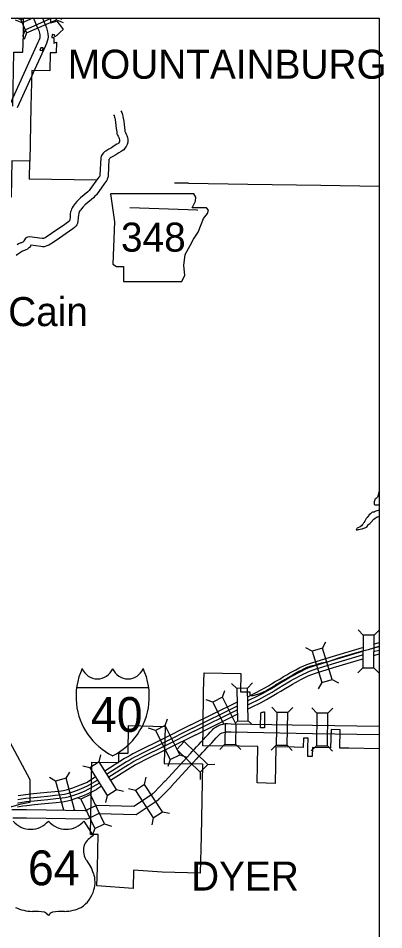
# Model space of a CAD drawing. Extents: x 535214 to 694517, y 381272 to 484355.
# Drawn here: x 559659 to 566314, y 463649 to 480223 of the extents above; entities that cross this region are included whole.
import ezdxf

# ---------------------------------------------------------------- set-up
doc = ezdxf.new("R2010")
doc.units = 0
for name, color, linetype in [('1', 7, 'Continuous'), ('Level 11', 7, 'Continuous'), ('Level 15', 7, 'Continuous'), ('Level 19', 7, 'Continuous'), ('Level 20', 7, 'Continuous'), ('Level 21', 7, 'Continuous'), ('Level 22', 7, 'Continuous'), ('Level 23', 7, 'Continuous'), ('Level 24', 7, 'Continuous'), ('Level 6', 7, 'Continuous'), ('Level 8', 7, 'Continuous'), ('Level 9', 7, 'Continuous')]:
    doc.layers.add(name, color=color, linetype=linetype)

msp = doc.modelspace()

# ---------------------------------------------------------------- linework, layer by layer
at = {"layer": '1'}
msp.add_lwpolyline([(535214, 480223), (566227, 480223), (566227, 448175), (535214, 448175)], close=True, dxfattribs=at)
at = {"layer": 'Level 11'}
for points in [[(561529, 478538), (561544, 478509), (561558, 478470), (561565, 478439), (561572, 478405), (561580, 478349), (561587, 478289), (561593, 478239), (561601, 478180), (561603, 478161), (561604, 478160), (561610, 478148), (561625, 478118), (561636, 478090), (561648, 478052), (561656, 478017), (561655, 477972), (561644, 477927), (561627, 477891), (561603, 477858), (561579, 477832), (561554, 477815), (561535, 477803), (561488, 477774), (561434, 477740), (561384, 477711), (561336, 477683), (561325, 477675), (561318, 477669), (561313, 477663), (561312, 477659)], [(561395, 478469), (561406, 478449), (561414, 478426), (561419, 478407), (561424, 478380), (561431, 478329), (561438, 478272), (561444, 478221), (561452, 478159), (561457, 478123), (561467, 478097), (561477, 478079), (561488, 478056), (561495, 478039), (561503, 478014), (561505, 478002), (561505, 477991), (561502, 477977), (561497, 477967), (561488, 477954), (561480, 477946), (561471, 477940), (561457, 477931), (561408, 477901), (561356, 477868), (561309, 477841), (561254, 477809), (561231, 477792), (561210, 477773), (561187, 477746), (561171, 477715), (561162, 477683)], [(561162, 477683), (561145, 477371), (561143, 477358), (561142, 477354), (561139, 477348), (561135, 477342), (561104, 477301), (560966, 477111), (560948, 477091), (560925, 477069), (560795, 476957), (560772, 476938), (560755, 476920), (560725, 476889), (560694, 476854), (560675, 476828), (560658, 476804), (560640, 476774), (560629, 476752), (560621, 476730), (560614, 476701), (560608, 476669), (560603, 476609), (560598, 476559), (560595, 476544), (560595, 476544), (560592, 476539), (560589, 476536), (560580, 476527), (560558, 476508), (560509, 476473), (560265, 476307), (560170, 476241), (560153, 476232), (560134, 476224), (560118, 476219), (560110, 476218), (560102, 476217), (560093, 476218), (559867, 476251), (559828, 476241), (559795, 476223), (559772, 476196), (559763, 476178), (559760, 476169), (559759, 476167), (559756, 476164), (559748, 476157), (559741, 476150), (559732, 476146), (559721, 476141), (559705, 476137), (559667, 476119), (559638, 476101)], [(561311, 477660), (561294, 477355), (561290, 477326), (561281, 477297), (561270, 477275), (561260, 477259), (561225, 477212), (561082, 477015), (561056, 476987), (561028, 476959), (560892, 476843), (560875, 476828), (560863, 476816), (560836, 476787), (560811, 476759), (560797, 476741), (560784, 476723), (560771, 476700), (560766, 476691), (560764, 476687), (560761, 476671), (560757, 476651), (560753, 476595), (560747, 476536), (560738, 476493), (560725, 476468), (560712, 476448), (560697, 476432), (560681, 476416), (560651, 476391), (560595, 476350), (560350, 476183), (560250, 476114), (560219, 476097), (560183, 476082), (560152, 476073), (560129, 476069), (560100, 476066), (560073, 476070), (559892, 476096), (559881, 476079), (559862, 476057), (559846, 476043), (559827, 476026), (559798, 476011), (559771, 475999), (559757, 475995), (559738, 475986), (559718, 475975), (559667, 475941), (559622, 475911)]]:
    msp.add_lwpolyline(points, dxfattribs=at)
at = {"layer": 'Level 15'}
for points in [[(559938, 480223), (559946, 480205), (559995, 480094), (560018, 480039), (560033, 480003), (560046, 479950), (560050, 479924), (560051, 479886), (560050, 479868), (560046, 479850), (560035, 479819), (560019, 479785), (559505, 478654)], [(560102, 480223), (560133, 480152), (560156, 480096), (560175, 480050), (560194, 479978), (560199, 479937), (560202, 479885), (560199, 479844), (560189, 479805), (560174, 479763), (560156, 479723), (559641, 478593)], [(562794, 466855), (562827, 466891), (562868, 466933), (562906, 466975), (562947, 467017), (562990, 467064), (563031, 467108), (563070, 467150), (563114, 467199), (563154, 467241), (563196, 467286), (563215, 467307), (563235, 467321), (563255, 467335), (563278, 467350), (563298, 467359), (563320, 467369), (563355, 467379), (563387, 467389), (563431, 467397), (563471, 467397), (563538, 467396), (565018, 467368), (566227, 467351)], [(562903, 466753), (562935, 466787), (562977, 466829), (563016, 466872), (563056, 466914), (563100, 466962), (563141, 467006), (563181, 467049), (563224, 467097), (563263, 467138), (563305, 467183), (563315, 467194), (563322, 467199), (563338, 467210), (563350, 467218), (563360, 467222), (563373, 467228), (563397, 467235), (563422, 467243), (563445, 467247), (563470, 467247), (563536, 467246), (565015, 467218), (566227, 467201)], [(562793, 466855), (562333, 466353)], [(562904, 466754), (562443, 466251)], [(559543, 465836), (559810, 465834), (560876, 465816), (560884, 465816), (560891, 465819), (560921, 465834), (561088, 465913), (561762, 465898), (562106, 466122), (562117, 466130), (562128, 466140), (562334, 466354)], [(559561, 465686), (559808, 465684), (560879, 465666), (560908, 465667), (560931, 465673), (560954, 465683), (560986, 465699), (561120, 465762), (561805, 465747), (562190, 465998), (562212, 466013), (562233, 466033), (562442, 466250)]]:
    msp.add_lwpolyline(points, dxfattribs=at)
at = {"layer": 'Level 19'}
for points in [[(563836, 467886), (563980, 467955), (564084, 468009), (564213, 468085), (564269, 468119), (564337, 468161), (564419, 468208), (564491, 468251), (564551, 468286), (564604, 468319), (564667, 468353), (564710, 468377), (564787, 468416), (564858, 468450), (564915, 468473), (565005, 468505), (565339, 468607), (565926, 468782)], [(566128, 468843), (566227, 468872)], [(566129, 468706), (566227, 468735)], [(566134, 468773), (566227, 468801)], [(563836, 467739), (563888, 467765), (564039, 467838), (564147, 467895), (564279, 467972), (564337, 468006), (564404, 468048), (564485, 468095), (564557, 468138), (564618, 468173), (564670, 468205), (564730, 468238), (564772, 468261), (564845, 468298), (564911, 468329), (564962, 468350), (565046, 468380), (565377, 468482), (565928, 468646)], [(563844, 467813), (563860, 467821), (564011, 467894), (564117, 467949), (564248, 468026), (564305, 468060), (564372, 468102), (564453, 468149), (564526, 468192), (564586, 468227), (564639, 468259), (564700, 468293), (564743, 468316), (564818, 468354), (564885, 468387), (564939, 468409), (565026, 468440), (565359, 468542), (565932, 468712)], [(563846, 467668), (563918, 467703), (564070, 467777), (564181, 467834), (564314, 467913), (564373, 467948), (564440, 467989), (564520, 468036), (564592, 468079), (564653, 468114), (564705, 468146), (564763, 468178), (564804, 468200), (564875, 468237), (564938, 468266), (564986, 468286), (565068, 468315), (565397, 468416), (565933, 468575)], [(566133, 468635), (566227, 468664)], [(562802, 467375), (563641, 467790)], [(562833, 467313), (563639, 467712)], [(562860, 467257), (563647, 467647)], [(562891, 467196), (563646, 467569)], [(562802, 467375), (562275, 467111), (561842, 466899), (561797, 466874), (561747, 466848), (561696, 466820), (561642, 466788), (561596, 466762), (561237, 466535)], [(562833, 467313), (562306, 467050), (561874, 466837), (561829, 466813), (561779, 466788), (561731, 466760), (561677, 466728), (561632, 466703), (561269, 466474)], [(562861, 467257), (562333, 466994), (561902, 466782), (561858, 466758), (561809, 466733), (561762, 466706), (561708, 466674), (561664, 466649), (561306, 466423)], [(562891, 467196), (562364, 466932), (561934, 466721), (561890, 466697), (561842, 466672), (561797, 466647), (561743, 466615), (561699, 466590), (561338, 466363)], [(561063, 466426), (560918, 466334)], [(559651, 465953), (559665, 465957), (559731, 465969), (559806, 465980), (559951, 465994), (560069, 466006), (560201, 466018), (560342, 466033), (560459, 466045), (560512, 466053), (560593, 466075), (560692, 466104), (560792, 466140), (560880, 466176), (560947, 466210), (561144, 466321)], [(559652, 466018), (559721, 466031), (559799, 466042), (559945, 466056), (560063, 466068), (560195, 466080), (560335, 466095), (560452, 466107), (560499, 466114), (560576, 466135), (560672, 466164), (560769, 466198), (560854, 466233), (560918, 466265), (561105, 466371)], [(559659, 466089), (559710, 466099), (559791, 466110), (559938, 466124), (560057, 466136), (560188, 466148), (560328, 466163), (560443, 466175), (560485, 466182), (560557, 466201), (560651, 466229), (560745, 466263), (560918, 466334)], [(561175, 466260), (561083, 466201)], [(559646, 465882), (559679, 465890), (559742, 465901), (559814, 465911), (559958, 465925), (560076, 465937), (560208, 465949), (560349, 465964), (560468, 465977), (560526, 465985), (560612, 466008), (560713, 466039), (560816, 466076), (560909, 466114), (561083, 466201)]]:
    msp.add_lwpolyline(points, dxfattribs=at)
at = {"layer": 'Level 20'}
for p, q in [((559733, 480138), (559610, 480186)), ((559708, 480196), (559639, 480223)), ((560357, 480196), (560480, 480148)), ((560409, 480223), (560454, 480206)), ((559787, 480015), (559739, 479892)), ((559813, 479957), (559765, 479834)), ((565938, 469006), (565845, 469100)), ((566136, 469005), (566227, 469096)), ((565009, 468712), (564892, 468774)), ((565198, 468770), (565260, 468887)), ((565935, 468412), (565841, 468319)), ((566133, 468411), (566226, 468318)), ((563636, 468037), (563541, 468129)), ((563834, 468041), (563925, 468136)), ((565183, 468144), (565121, 468028)), ((565372, 468202), (565489, 468140)), ((563380, 467876), (563423, 468001)), ((563834, 468041), (563636, 468037)), ((563636, 468037), (563648, 467443)), ((563846, 467447), (563834, 468041)), ((563203, 467788), (563078, 467830)), ((563380, 467876), (563203, 467788)), ((563203, 467788), (563397, 467396)), ((563619, 467394), (563380, 467876)), ((564367, 467602), (564276, 467697)), ((564565, 467599), (564660, 467690)), ((565097, 467589), (565005, 467684)), ((565295, 467586), (565389, 467678)), ((562335, 467361), (562377, 467487)), ((563648, 467443), (563624, 467418)), ((563648, 467443), (563846, 467447)), ((563846, 467447), (563903, 467392)), ((562158, 467273), (562033, 467314)), ((563426, 467398), (563421, 467021)), ((563619, 467018), (563624, 467392)), ((562683, 467070), (562545, 466928)), ((562683, 467070), (562683, 467088)), ((563109, 466656), (562683, 467070)), ((562545, 466928), (562971, 466514)), ((563421, 467021), (563327, 466929)), ((563421, 467021), (563619, 467018)), ((563619, 467018), (563711, 466924)), ((564356, 467008), (564261, 466917)), ((564554, 467005), (564645, 466910)), ((565088, 466995), (564994, 466903)), ((565286, 466992), (565378, 466898)), ((561131, 466701), (561161, 466830)), ((562424, 466742), (562382, 466616)), ((562601, 466830), (562726, 466788)), ((560964, 466596), (560835, 466625)), ((562971, 466514), (563109, 466656)), ((563109, 466656), (563241, 466658)), ((560341, 466352), (560226, 466417)), ((560532, 466403), (560598, 466517)), ((561959, 466292), (561986, 466421)), ((562971, 466514), (562973, 466382)), ((560532, 466403), (560341, 466352)), ((560341, 466352), (560481, 465829)), ((560686, 465829), (560532, 466403)), ((560976, 466111), (560797, 466026)), ((560976, 466111), (560991, 466152)), ((561230, 465574), (560976, 466111)), ((561281, 466093), (561251, 465965)), ((561448, 466199), (561577, 466170)), ((561793, 466184), (561664, 466211)), ((560797, 466026), (560740, 466046)), ((560797, 466026), (561051, 465489)), ((560668, 465824), (560686, 465829)), ((560686, 465829), (560697, 465822)), ((562283, 465794), (562413, 465767)), ((562117, 465686), (562090, 465557)), ((561051, 465489), (561007, 465365)), ((561051, 465489), (561230, 465574)), ((561230, 465574), (561355, 465530))]:
    msp.add_line(p, q, dxfattribs=at)
for points in [[(559769, 480223), (559708, 480196), (559787, 480015), (560262, 480223)], [(559927, 480223), (559733, 480138), (559813, 479957), (560357, 480196), (560345, 480223)]]:
    msp.add_lwpolyline(points, dxfattribs=at)
for points in [[(566133, 468411), (566136, 469005), (565938, 469006), (565935, 468412)], [(565372, 468202), (565198, 468770), (565009, 468712), (565183, 468144)], [(564367, 467602), (564356, 467008), (564554, 467005), (564565, 467599)], [(565286, 466992), (565295, 467586), (565097, 467589), (565088, 466995)], [(562601, 466830), (562335, 467361), (562158, 467273), (562424, 466742)], [(561448, 466199), (561131, 466701), (560964, 466596), (561281, 466093)], [(561793, 466184), (562117, 465686), (562283, 465794), (561959, 466292)]]:
    msp.add_lwpolyline(points, close=True, dxfattribs=at)
at = {"layer": 'Level 21'}
msp.add_lwpolyline([(561338, 477029), (561414, 476522), (561380, 475752), (561448, 475710), (561574, 475710), (561574, 475439), (562640, 475439), (562691, 475549), (562674, 475727), (562699, 475930), (562792, 476090), (562852, 476209), (562936, 476336), (562987, 476471), (563029, 476581), (563105, 476674), (563122, 476733), (563089, 476776), (562826, 476776), (562886, 476894), (562894, 476970), (562859, 477029)], close=True, dxfattribs=at)
at = {"layer": 'Level 22'}
msp.add_line((560852, 465626), (561025, 465358), dxfattribs=at)
for centre, radius, start, end in [((559888, 465897), 421, 220.075, 319.6701), ((560530, 465897), 421, 220.3299, 319.925), ((561251, 464970), 450, 120.0117, 149.2191), ((561153, 465088), 308, 158.7892, 211.1895), ((560346, 464456), 719, 17.3087, 41.0435), ((560584, 464515), 475, 342.6181, 19.0424), ((560506, 464517), 550, 302.8688, 344.8926), ((559921, 464690), 706, 244.0771, 269.5779), ((559938, 462691), 1293, 81.1942, 90.9539), ((560099, 463850), 124, 28.0342, 72.9864), ((560318, 463850), 124, 107.0136, 151.9658), ((560480, 462691), 1293, 89.0461, 98.8058), ((560496, 464690), 706, 270.4221, 295.9229)]:
    msp.add_arc(centre, radius, start, end, dxfattribs=at)
at = {"layer": 'Level 23'}
msp.add_line((560723, 468054), (562034, 468054), dxfattribs=at)
for centre, radius, start, end in [((561941, 467883), 1230, 155.2204, 185.7928), ((561102, 468511), 300, 202.1459, 337.3414), ((561655, 468511), 300, 202.6586, 337.8541), ((560816, 467883), 1230, 354.2072, 24.7796), ((561919, 467893), 1209, 186.3923, 243.4571), ((560838, 467893), 1209, 296.5429, 353.6077)]:
    msp.add_arc(centre, radius, start, end, dxfattribs=at)
at = {"layer": 'Level 6'}
for points in [[(559754, 479934), (559756, 480223)], [(560250, 480223), (560249, 480142), (560360, 480170), (560445, 480059), (560475, 480018), (560421, 479969), (560374, 479922), (560366, 479915), (560361, 479911), (560356, 479907), (560351, 479904), (560344, 479900), (560331, 479894), (560319, 479890), (560319, 479924), (560275, 479925)], [(559559, 478622), (559573, 479279), (559580, 479608), (559746, 479605), (559754, 479934)], [(560275, 479925), (560272, 479875), (560310, 479875), (560308, 479771), (560356, 479791), (560353, 479592), (560240, 479595), (560234, 479267), (559906, 479274)], [(560074, 479688), (560055, 479645), (560095, 479637), (560119, 479674), (560101, 479683), (560074, 479688)], [(559906, 479274), (559892, 478617)], [(559892, 478617), (559885, 478287), (559878, 477956), (559871, 477626)], [(559871, 477626), (559541, 477631), (559535, 477301), (559530, 476972), (559201, 476978), (558872, 476984), (558874, 477148), (558665, 476748), (558623, 476777), (558609, 476788), (558599, 476800), (558592, 476806), (558576, 476817), (558564, 476825), (558552, 476832), (558540, 476840), (558542, 476990), (558567, 476990), (558880, 477560)], [(563875, 467974), (563875, 467912), (563897, 467909), (563921, 467910), (563937, 467911), (563960, 467916), (563980, 467921), (563999, 467927), (564019, 467934), (564037, 467940), (564086, 467957), (564127, 467975), (564166, 467996), (564214, 468023), (564257, 468049), (564300, 468073), (564333, 468092), (564350, 468107), (564374, 468120), (564396, 468132), (564422, 468148), (564444, 468161), (564465, 468173), (564488, 468187), (564508, 468199), (564524, 468208), (564573, 468234), (564660, 468287), (564681, 468302), (564780, 468356), (564813, 468372), (564834, 468382), (564855, 468393), (564872, 468401), (564891, 468410), (564908, 468417), (564929, 468427), (564961, 468436), (564974, 468440), (564993, 468446), (565006, 468450), (565020, 468455), (565047, 468463), (565071, 468469), (565092, 468476), (565119, 468484), (565178, 468501), (565219, 468508), (565305, 468529), (565372, 468549), (565513, 468601), (565720, 468663), (565953, 468724), (566036, 468746), (566227, 468806)], [(563688, 466985), (563020, 466996), (563024, 467327), (563032, 467986), (563043, 468321)], [(563043, 468321), (563713, 468311)], [(563713, 468311), (563705, 467976)], [(563705, 467976), (563875, 467974)], [(564068, 467321), (564075, 467593)], [(564075, 467593), (564088, 467597), (564102, 467603), (564116, 467607), (564133, 467612), (564144, 467614)], [(564144, 467614), (564141, 467319)], [(561490, 466688), (561493, 466862), (561660, 466858), (561668, 467362), (562337, 467343)], [(562337, 467343), (562337, 467340), (562315, 466675)], [(564141, 467319), (564068, 467321)], [(565353, 467289), (565346, 466956)], [(565518, 467285), (565353, 467289)], [(565512, 466953), (565518, 467285)], [(559501, 467074), (559871, 466380), (559871, 465960), (559810, 465953), (559706, 465934), (559520, 465877)], [(565012, 466800), (564929, 466802), (564932, 466964), (564935, 467130), (564852, 467131), (564849, 466965), (564683, 466968), (564351, 466974)], [(564019, 466979), (563688, 466985)], [(564006, 466318), (564013, 466648), (564019, 466979)], [(564351, 466974), (564345, 466642), (564338, 466311)], [(565015, 466962), (565012, 466800)], [(565346, 466956), (565015, 466962)], [(566227, 466939), (565677, 466950), (565512, 466953)], [(560973, 465383), (560998, 466698)], [(560998, 466698), (561490, 466688)], [(562315, 466675), (563016, 466664), (562992, 465345)], [(564338, 466311), (564006, 466318)], [(561114, 465380), (560973, 465383)], [(561092, 464445), (561100, 464775), (561114, 465380)], [(562992, 465345), (562974, 464681), (562280, 464696)], [(561759, 464731), (561751, 464400)], [(562280, 464696), (561759, 464731)], [(561751, 464400), (561092, 464445)]]:
    msp.add_lwpolyline(points, dxfattribs=at)
at = {"layer": 'Level 8'}
for points in [[(559867, 477628), (559856, 477300)], [(561083, 477278), (559856, 477300)], [(562760, 477225), (562507, 477227)], [(562760, 477225), (563839, 477206), (565168, 477187), (566227, 477167)], [(562924, 476734), (561689, 476773)], [(562924, 476726), (562924, 476734)]]:
    msp.add_lwpolyline(points, dxfattribs=at)
at = {"layer": 'Level 9'}
for points in [[(566227, 471614), (566225, 471610), (566220, 471590), (566215, 471569), (566212, 471549), (566207, 471530), (566200, 471517), (566187, 471503), (566172, 471489), (566157, 471477), (566148, 471466), (566142, 471449), (566139, 471431), (566139, 471413), (566139, 471397), (566139, 471387), (566143, 471379), (566151, 471375), (566168, 471373), (566198, 471373), (566227, 471373)], [(566227, 471275), (566209, 471271), (566187, 471264), (566170, 471259), (566156, 471252), (566140, 471244), (566126, 471243), (566114, 471245), (566108, 471241), (566097, 471233), (566070, 471209), (566050, 471193), (566027, 471168), (566010, 471147), (565994, 471128), (565987, 471112), (565966, 471078), (565949, 471053), (565936, 471032), (565920, 471011), (565905, 470993), (565886, 470978), (565869, 470969), (565844, 470958), (565828, 470950), (565821, 470940), (565818, 470932), (565814, 470929), (565811, 470924), (565809, 470921), (565817, 470918), (565832, 470920), (565853, 470925), (565886, 470932), (565917, 470937), (565932, 470944), (565949, 470951), (565968, 470956)], [(565968, 470956), (565986, 470963), (565995, 470970), (566011, 470983), (566031, 471009), (566042, 471021), (566058, 471036), (566082, 471061), (566099, 471081), (566117, 471100), (566135, 471114), (566158, 471130), (566176, 471145), (566194, 471156), (566208, 471160), (566226, 471161), (566227, 471161)]]:
    msp.add_lwpolyline(points, dxfattribs=at)

# ---------------------------------------------------------------- texts
at = {"layer": 'Level 21'}
msp.add_text('348', height=528, dxfattribs=at).set_placement((561530, 475979))
at = {"layer": 'Level 22'}
msp.add_text('64', height=633.6, dxfattribs=at).set_placement((559835, 464458))
at = {"layer": 'Level 23'}
msp.add_text('40', height=633.6, dxfattribs=at).set_placement((560981, 467246))
at = {"layer": 'Level 24'}
msp.add_text('Cain', height=528, dxfattribs=at).set_placement((559477, 474625))
at = {"layer": 'Level 6'}
for s, p in [('MOUNTAINBURG', (560561, 479123)), ('DYER', (562806, 464362))]:
    msp.add_text(s, height=528, dxfattribs=at).set_placement(p)

doc.saveas('drawing.dxf')
